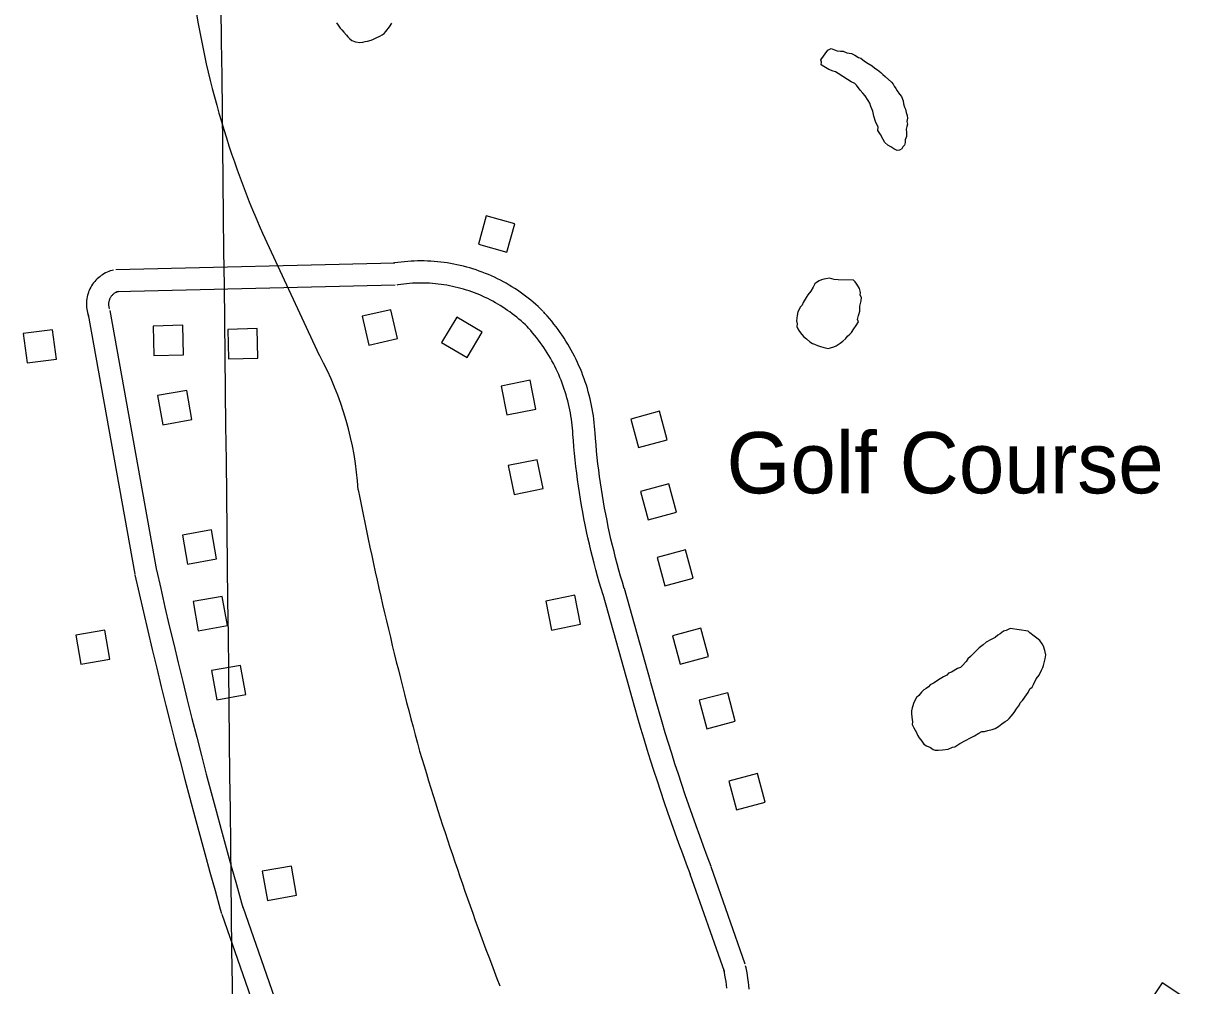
# Model space of a CAD drawing. Extents: x 3683402 to 3721514, y 487807 to 513565.
# Drawn here: x 3692628 to 3694204, y 495317 to 496621 of the extents above; entities that cross this region are included whole.
import ezdxf

# ---------------------------------------------------------------- set-up
doc = ezdxf.new("R2010")
doc.units = 0
for name, color, linetype in [('V-BLDG-IDEN', 7, 'Continuous'), ('V-BLDG-OTLN', 7, 'Continuous'), ('V-GRID-MAJR', 7, 'Continuous'), ('V-ROAD-CNTR', 7, 'Continuous'), ('V-TOPO-SHOR', 7, 'Continuous')]:
    doc.layers.add(name, color=color, linetype=linetype)

msp = doc.modelspace()

# ---------------------------------------------------------------- linework, layer by layer
at = {"layer": 'V-BLDG-OTLN'}
for points in [[(3693245, 496321.7), (3693283.6, 496311.1), (3693294.2, 496349.6), (3693255.6, 496360.3)], [(3693126.4, 496233), (3693087.4, 496224.2), (3693096.3, 496185.2), (3693135.2, 496194)], [(3693250, 496202.6), (3693215.7, 496223.1), (3693195.1, 496188.8), (3693229.5, 496168.2)], [(3692673.2, 496166.2), (3692668, 496205.9), (3692628.4, 496200.7), (3692633.5, 496161.1)], [(3692844.4, 496211.9), (3692804.4, 496210.9), (3692805.3, 496170.9), (3692845.3, 496171.9)], [(3692945.3, 496207.4), (3692905.3, 496206.4), (3692906.2, 496166.4), (3692946.2, 496167.4)], [(3693322.8, 496098.3), (3693315, 496137.5), (3693275.7, 496129.7), (3693283.5, 496090.5)], [(3692810.4, 496116.7), (3692817.5, 496077.3), (3692856.8, 496084.4), (3692849.8, 496123.8)], [(3693451.6, 496085), (3693461.9, 496046.4), (3693500.6, 496056.7), (3693490.2, 496095.4)], [(3693332.4, 495990.7), (3693324.6, 496029.9), (3693285.4, 496022.1), (3693293.2, 495982.9)], [(3693464.3, 495987), (3693474.7, 495948.4), (3693513.3, 495958.7), (3693502.9, 495997.4)], [(3692843.9, 495927.8), (3692850.9, 495888.5), (3692890.3, 495895.6), (3692883.2, 495934.9)], [(3693487, 495897.5), (3693497.3, 495858.9), (3693536, 495869.2), (3693525.6, 495907.9)], [(3692858.4, 495837.6), (3692865.5, 495798.2), (3692904.9, 495805.3), (3692897.8, 495844.7)], [(3693383.2, 495806.9), (3693375.4, 495846.2), (3693336.2, 495838.3), (3693344, 495799.1)], [(3692745.7, 495759.7), (3692738.8, 495799.1), (3692699.4, 495792.2), (3692706.3, 495752.8)], [(3693507.6, 495791.5), (3693518, 495752.8), (3693556.6, 495763.2), (3693546.2, 495801.8)], [(3692883.3, 495744.2), (3692890.4, 495704.8), (3692929.7, 495711.9), (3692922.7, 495751.2)], [(3693543.9, 495703.9), (3693554.3, 495665.2), (3693592.9, 495675.6), (3693582.6, 495714.2)], [(3693584.3, 495594.2), (3693594.7, 495555.6), (3693633.3, 495566), (3693623, 495604.6)], [(3692952.1, 495472.3), (3692959.2, 495432.9), (3692998.5, 495440), (3692991.5, 495479.4)], [(3694182.4, 495265.6), (3694204.4, 495299), (3694171, 495321), (3694149, 495287.6)]]:
    msp.add_lwpolyline(points, close=True, dxfattribs=at)
at = {"layer": 'V-GRID-MAJR'}
msp.add_spline([(3692934.8, 493283.3), (3692866.1, 499341.9), (3692797.3, 505402.5), (3692796.2, 505494.7)], degree=3, dxfattribs=at)
at = {"layer": 'V-ROAD-CNTR'}
for points in [[(3692952.5, 496336.6), (3693029.4, 496171.4)], [(3693131.6, 496296.3), (3692753.8, 496287.3)], [(3693332.3, 496231.1), (3693329.2, 496234.2), (3693326, 496237.2), (3693322.6, 496240.2), (3693319.3, 496243.2), (3693315.8, 496246), (3693312.3, 496248.8), (3693308.8, 496251.6), (3693305.2, 496254.2), (3693301.6, 496256.8), (3693297.9, 496259.4), (3693294.1, 496261.8), (3693290.3, 496264.2), (3693286.5, 496266.5), (3693282.6, 496268.8), (3693278.7, 496270.9), (3693274.8, 496273), (3693270.8, 496275), (3693266.7, 496277), (3693262.7, 496278.8), (3693258.5, 496280.6), (3693254.4, 496282.3), (3693250.2, 496283.9), (3693246, 496285.5), (3693241.8, 496286.9), (3693237.5, 496288.3), (3693233.3, 496289.6), (3693229, 496290.9), (3693224.6, 496292), (3693220.3, 496293), (3693215.9, 496294), (3693211.5, 496294.9), (3693207.1, 496295.7), (3693202.7, 496296.4), (3693198.3, 496297.1), (3693193.8, 496297.6), (3693189.4, 496298.1), (3693184.9, 496298.5), (3693180.5, 496298.7), (3693176, 496299), (3693171.5, 496299.1), (3693167, 496299.1), (3693162.6, 496299.1), (3693158.1, 496298.9), (3693153.6, 496298.7), (3693149.2, 496298.4), (3693144.7, 496298), (3693140.2, 496297.6), (3693135.8, 496297), (3693131.4, 496296.4), (3693129.6, 496296.1)], [(3692750.5, 496286.8), (3692748.6, 496286.3), (3692746.3, 496285.6), (3692744.1, 496284.8), (3692741.9, 496283.9), (3692739.8, 496282.9), (3692737.7, 496281.8), (3692735.7, 496280.5), (3692733.8, 496279.2), (3692731.9, 496277.8), (3692730.1, 496276.3), (3692728.3, 496274.7), (3692726.7, 496273), (3692725.1, 496271.2), (3692723.6, 496269.4), (3692722.3, 496267.5), (3692721, 496265.5), (3692719.8, 496263.5), (3692718.7, 496261.4), (3692717.7, 496259.2), (3692716.8, 496257.1), (3692716.1, 496254.8), (3692715.4, 496252.6), (3692714.9, 496250.3), (3692714.5, 496247.9), (3692714.1, 496245.6), (3692714, 496243.3), (3692713.9, 496240.9), (3692713.9, 496238.5), (3692714.1, 496236.2), (3692714.3, 496233.8), (3692714.7, 496231.5), (3692715.2, 496229.2), (3692715.8, 496226.9), (3692716.5, 496224.8), (3692716.7, 496224.3)], [(3693132.3, 496266.3), (3692754.6, 496257.3)], [(3693311.4, 496209.7), (3693308.5, 496212.5), (3693305.6, 496215.1), (3693302.7, 496217.8), (3693299.8, 496220.3), (3693296.8, 496222.8), (3693293.8, 496225.3), (3693290.7, 496227.7), (3693287.5, 496230), (3693284.4, 496232.2), (3693281.1, 496234.4), (3693277.9, 496236.6), (3693274.6, 496238.7), (3693271.2, 496240.7), (3693267.9, 496242.6), (3693264.4, 496244.5), (3693261, 496246.4), (3693257.5, 496248.1), (3693254, 496249.8), (3693250.4, 496251.4), (3693246.9, 496253), (3693243.3, 496254.5), (3693239.6, 496255.9), (3693236, 496257.2), (3693232.3, 496258.5), (3693228.6, 496259.7), (3693224.8, 496260.8), (3693221.1, 496261.9), (3693217.3, 496262.9), (3693213.5, 496263.8), (3693209.7, 496264.7), (3693205.9, 496265.4), (3693202, 496266.1), (3693198.2, 496266.8), (3693194.3, 496267.3), (3693190.4, 496267.8), (3693186.6, 496268.2), (3693182.7, 496268.5), (3693178.8, 496268.8), (3693174.9, 496269), (3693171, 496269.1), (3693167.1, 496269.1), (3693163.2, 496269.1), (3693159.3, 496269), (3693155.4, 496268.8), (3693151.5, 496268.5), (3693147.6, 496268.2), (3693143.7, 496267.8), (3693139.8, 496267.3), (3693135.9, 496266.7), (3693134.3, 496266.4)], [(3692757.9, 496257.7), (3692756.7, 496257.4), (3692755.9, 496257.2), (3692755.1, 496256.9), (3692754.3, 496256.5), (3692753.5, 496256.2), (3692752.7, 496255.8), (3692752, 496255.3), (3692751.2, 496254.8), (3692750.5, 496254.3), (3692749.9, 496253.7), (3692749.2, 496253.1), (3692748.6, 496252.5), (3692748, 496251.9), (3692747.5, 496251.2), (3692747, 496250.5), (3692746.5, 496249.7), (3692746.1, 496249), (3692745.7, 496248.2), (3692745.3, 496247.4), (3692745, 496246.6), (3692744.7, 496245.8), (3692744.5, 496245), (3692744.3, 496244.1), (3692744.1, 496243.3), (3692744, 496242.4), (3692743.9, 496241.5), (3692743.9, 496240.6), (3692743.9, 496239.8), (3692744, 496238.9), (3692744.1, 496238), (3692744.2, 496237.2), (3692744.4, 496236.3), (3692744.6, 496235.5), (3692744.9, 496234.5), (3692745, 496234.4)], [(3692745.6, 496232), (3692808.9, 495879.9)], [(3692716.1, 496226.7), (3692779.3, 495874.6)], [(3693402.9, 496066), (3693402.6, 496070.5), (3693402.2, 496075.2), (3693401.7, 496079.9), (3693401.2, 496084.6), (3693400.6, 496089.3), (3693399.8, 496094), (3693399, 496098.6), (3693398.1, 496103.3), (3693397.2, 496107.9), (3693396.1, 496112.5), (3693395, 496117.1), (3693393.8, 496121.6), (3693392.5, 496126.2), (3693391.1, 496130.7), (3693389.6, 496135.2), (3693388.1, 496139.6), (3693386.5, 496144.1), (3693384.8, 496148.5), (3693383, 496152.8), (3693381.1, 496157.2), (3693379.2, 496161.5), (3693377.2, 496165.7), (3693375.1, 496170), (3693372.9, 496174.2), (3693370.7, 496178.3), (3693368.4, 496182.4), (3693366, 496186.5), (3693363.5, 496190.5), (3693361, 496194.5), (3693358.4, 496198.5), (3693355.7, 496202.4), (3693353, 496206.2), (3693350.2, 496210), (3693347.3, 496213.7), (3693344.3, 496217.4), (3693341.3, 496221), (3693338.2, 496224.6), (3693335.1, 496228.1), (3693332.9, 496230.5)], [(3693372.9, 496064.1), (3693372.7, 496068.4), (3693372.3, 496072.5), (3693371.9, 496076.7), (3693371.4, 496080.9), (3693370.9, 496085), (3693370.2, 496089.1), (3693369.5, 496093.3), (3693368.7, 496097.4), (3693367.9, 496101.5), (3693366.9, 496105.5), (3693365.9, 496109.6), (3693364.9, 496113.6), (3693363.7, 496117.6), (3693362.5, 496121.6), (3693361.2, 496125.6), (3693359.8, 496129.6), (3693358.4, 496133.5), (3693356.9, 496137.4), (3693355.3, 496141.3), (3693353.7, 496145.1), (3693351.9, 496148.9), (3693350.2, 496152.7), (3693348.3, 496156.5), (3693346.4, 496160.2), (3693344.4, 496163.9), (3693342.4, 496167.5), (3693340.2, 496171.1), (3693338.1, 496174.7), (3693335.8, 496178.2), (3693333.5, 496181.7), (3693331.1, 496185.1), (3693328.7, 496188.5), (3693326.2, 496191.9), (3693323.7, 496195.2), (3693321.1, 496198.5), (3693318.4, 496201.7), (3693315.7, 496204.9), (3693312.9, 496208), (3693310.8, 496210.2)], [(3693413.8, 495846.8), (3693411.2, 495855.2), (3693408.7, 495863.8), (3693406.3, 495872.3), (3693403.9, 495880.9), (3693401.7, 495889.5), (3693399.5, 495898.1), (3693397.3, 495906.8), (3693395.3, 495915.5), (3693393.3, 495924.1), (3693391.5, 495932.8), (3693389.7, 495941.6), (3693387.9, 495950.3), (3693386.3, 495959), (3693384.7, 495967.8), (3693383.3, 495976.6), (3693381.9, 495985.4), (3693380.5, 495994.2), (3693379.3, 496003), (3693378.1, 496011.8), (3693377.1, 496020.6), (3693376.1, 496029.5), (3693375.1, 496038.3), (3693374.3, 496047.2), (3693373.6, 496056.1), (3693373, 496063.9)], [(3693442.5, 495855.5), (3693440, 495863.8), (3693437.5, 495872.1), (3693435.2, 495880.4), (3693432.9, 495888.7), (3693430.7, 495897.1), (3693428.6, 495905.4), (3693426.5, 495913.8), (3693424.5, 495922.2), (3693422.6, 495930.6), (3693420.8, 495939), (3693419.1, 495947.5), (3693417.4, 495956), (3693415.8, 495964.4), (3693414.3, 495972.9), (3693412.9, 495981.4), (3693411.5, 495989.9), (3693410.2, 495998.5), (3693409, 496007), (3693407.9, 496015.6), (3693406.9, 496024.1), (3693405.9, 496032.7), (3693405, 496041.3), (3693404.2, 496049.9), (3693403.5, 496058.5), (3693402.9, 496066.2)], [(3692779.5, 495873.9), (3692785.2, 495848.6), (3692791.1, 495823.3), (3692797, 495798.1), (3692803, 495772.8), (3692809.1, 495747.6), (3692815.3, 495722.3), (3692821.5, 495697.1), (3692827.8, 495671.9), (3692834.2, 495646.8), (3692840.7, 495621.6), (3692847.2, 495596.5), (3692853.9, 495571.4), (3692860.6, 495546.3), (3692867.4, 495521.3), (3692874.2, 495496.2), (3692881.2, 495471.2), (3692888.2, 495446.2), (3692895.3, 495421.2), (3692897, 495415)], [(3692808.7, 495880.6), (3692814.5, 495855.3), (3692820.3, 495830.1), (3692826.2, 495805), (3692832.2, 495779.8), (3692838.3, 495754.6), (3692844.4, 495729.5), (3692850.6, 495704.4), (3692856.9, 495679.3), (3692863.3, 495654.2), (3692869.7, 495629.2), (3692876.3, 495604.1), (3692882.9, 495579.1), (3692889.5, 495554.1), (3692896.3, 495529.1), (3692903.1, 495504.2), (3692910.1, 495479.3), (3692917, 495454.4), (3692924.1, 495429.5), (3692925.9, 495423.2)], [(3693477.9, 495729.7), (3693442.6, 495855.2)], [(3693449, 495721.6), (3693413.7, 495847.1)], [(3693560.1, 495478.8), (3693554.9, 495492.6), (3693549.7, 495506.4), (3693544.7, 495520.2), (3693539.7, 495534.1), (3693534.7, 495548), (3693529.9, 495561.9), (3693525.1, 495575.9), (3693520.4, 495589.8), (3693515.8, 495603.8), (3693511.2, 495617.8), (3693506.8, 495631.9), (3693502.4, 495646), (3693498, 495660), (3693493.8, 495674.2), (3693489.6, 495688.3), (3693485.5, 495702.5), (3693481.5, 495716.6), (3693477.9, 495729.6)], [(3693532.1, 495468.1), (3693526.8, 495482), (3693521.6, 495496), (3693516.5, 495510), (3693511.4, 495524), (3693506.4, 495538), (3693501.5, 495552.1), (3693496.7, 495566.2), (3693491.9, 495580.3), (3693487.3, 495594.5), (3693482.7, 495608.7), (3693478.1, 495622.9), (3693473.7, 495637.1), (3693469.3, 495651.3), (3693465, 495665.6), (3693460.8, 495679.9), (3693456.7, 495694.2), (3693452.6, 495708.5), (3693449, 495721.6)], [(3693606.4, 495346.4), (3693560.3, 495478.4)], [(3693578.1, 495336.5), (3693531.9, 495468.5)], [(3692897.3, 495414.2), (3692968.6, 495209.4)], [(3692925.6, 495424), (3692997, 495219.2)], [(3693581.4, 495314.2), (3693580.9, 495318.6), (3693580.3, 495322.9), (3693579.6, 495327.2), (3693578.9, 495331.5), (3693578.1, 495335.8), (3693577.5, 495338.4)], [(3693611.7, 495312.6), (3693611.2, 495317.5), (3693610.6, 495322.3), (3693610, 495327.2), (3693609.2, 495332), (3693608.4, 495336.8), (3693607.5, 495341.5), (3693606.9, 495344.4)]]:
    msp.add_lwpolyline(points, dxfattribs=at)
for centre, radius, start, end in [((3694086.7, 496840.2), 1241, 186.8966, 203.9404), ((3692643.8, 495961.5), 439.1, 3.6165, 28.5606), ((3697884.3, 496932.6), 4894.1, 191.1142, 195.3734), ((3697160.6, 496821.2), 4167.6, 196.5342, 201.1525)]:
    msp.add_arc(centre, radius, start, end, dxfattribs=at)
at = {"layer": 'V-TOPO-SHOR'}
for points in [[(3693052.5, 496621.9), (3693054.9, 496618.7), (3693057.8, 496614.5), (3693060, 496612.3), (3693062.4, 496609.1), (3693066.1, 496605.2), (3693068, 496602.8), (3693070.9, 496599.8), (3693073.6, 496597.8), (3693078.5, 496596.1), (3693084.1, 496595.1), (3693088.5, 496595.6), (3693091.7, 496596.3), (3693094.8, 496596.7), (3693099.7, 496598.4), (3693102.7, 496599.6), (3693106.3, 496601.3), (3693111.2, 496603.7), (3693114.7, 496605.4), (3693117.1, 496607.4), (3693119.3, 496609.8), (3693124.3, 496616.1), (3693127.5, 496621.2)], [(3693718.2, 496584.8), (3693722.7, 496586.9), (3693727.2, 496585.3), (3693730.9, 496583.7), (3693735.3, 496583.5), (3693739.1, 496583.4), (3693744.2, 496581), (3693750.2, 496580.1), (3693754.6, 496577.7), (3693759.8, 496574.6), (3693762.8, 496573.7), (3693767.9, 496569.8), (3693773, 496566.7), (3693778.2, 496563.5), (3693781.8, 496560.4), (3693785.5, 496558.1), (3693789.9, 496554.2), (3693792.8, 496551.9), (3693795.7, 496548.8), (3693804.4, 496541.1), (3693806.6, 496538.8), (3693808, 496535.7), (3693810.2, 496532.7), (3693812.3, 496529.6), (3693815.2, 496525), (3693818.1, 496521.9), (3693820.2, 496515.9), (3693820.8, 496512.1), (3693822.2, 496507.6), (3693823.6, 496504.6), (3693824.2, 496500.1), (3693825.6, 496496.3), (3693826.2, 496492.5), (3693825.3, 496488), (3693826, 496484.3), (3693825.1, 496481.3), (3693824.3, 496477.6), (3693824.9, 496473.1), (3693824.7, 496467.9), (3693823.1, 496463.4), (3693823, 496459.7), (3693822.1, 496456), (3693819.8, 496453.8), (3693818.3, 496450.8), (3693815.2, 496449.4), (3693812.2, 496448.8), (3693807.8, 496451.1), (3693803.4, 496453.5), (3693799.7, 496455.9), (3693795.3, 496459.7), (3693793.2, 496463.5), (3693789.6, 496470.4), (3693786.1, 496475.7), (3693786.2, 496481), (3693784.1, 496484.8), (3693782.7, 496487.8), (3693780.6, 496495.4), (3693779.3, 496502.1), (3693777.9, 496505.2), (3693776.5, 496508.2), (3693775.2, 496512.7), (3693773, 496516.5), (3693768.7, 496522.7), (3693765.8, 496526.5), (3693762.2, 496530.3), (3693757.2, 496537.2), (3693755, 496539.5), (3693749.8, 496541.9), (3693744.7, 496545.1), (3693732.2, 496552.9), (3693728.5, 496555.3), (3693725.6, 496556.1), (3693719.6, 496558.5), (3693713, 496562.5), (3693709.3, 496564.8), (3693709.5, 496568.6), (3693708.8, 496571.6), (3693718.2, 496584.8)], [(3693732.2, 496273.7), (3693726.9, 496273.9), (3693720.3, 496275.6), (3693715.7, 496275), (3693712.7, 496274.3), (3693709.7, 496273.6), (3693706.7, 496272.2), (3693702.9, 496270.1), (3693700.6, 496267.9), (3693698.2, 496263.5), (3693695, 496258.4), (3693691.2, 496253.2), (3693688.8, 496249.6), (3693684.9, 496242.9), (3693683.3, 496239.2), (3693680.9, 496236.3), (3693679.3, 496233.4), (3693677.8, 496230.4), (3693676.9, 496225.2), (3693675.9, 496217.8), (3693676.5, 496214), (3693676.4, 496210.3), (3693677.8, 496207.2), (3693679.9, 496203.4), (3693682.8, 496199.6), (3693685.7, 496196.5), (3693689.4, 496193.4), (3693693.8, 496189.5), (3693697.4, 496187.2), (3693700.4, 496186.3), (3693704.1, 496184.7), (3693708.5, 496183.1), (3693711.5, 496182.3), (3693715.2, 496181.4), (3693718.9, 496180.6), (3693722, 496181.2), (3693726.5, 496182.6), (3693729.5, 496184), (3693734.9, 496187.6), (3693738.7, 496190.4), (3693742.5, 496194.1), (3693744.9, 496197), (3693748, 496199.9), (3693750.3, 496202.1), (3693753.4, 496207.2), (3693756.5, 496211.6), (3693759.7, 496216.8), (3693758.3, 496219.8), (3693759.9, 496225), (3693760.8, 496228), (3693761.6, 496230.9), (3693761.8, 496237.7), (3693762.7, 496241.4), (3693763.5, 496245.1), (3693763.7, 496249.6), (3693762.2, 496252.6), (3693762.4, 496256.4), (3693761, 496261.6), (3693757.5, 496267.7), (3693755.3, 496270.8), (3693753.1, 496273.1), (3693732.2, 496273.7)], [(3693965.2, 495801.3), (3693959.9, 495798.4), (3693956.1, 495797.8), (3693951.5, 495794.2), (3693948.5, 495792), (3693944.7, 495789.1), (3693939.3, 495786.3), (3693932.5, 495782.8), (3693928.6, 495779.1), (3693923.3, 495774.8), (3693921, 495772.6), (3693918.7, 495770.4), (3693915.6, 495767.5), (3693911.7, 495763.2), (3693907.9, 495760.3), (3693905.5, 495756.6), (3693900.1, 495750.8), (3693897.8, 495748.6), (3693894, 495747.2), (3693885.6, 495742.2), (3693881.9, 495740.8), (3693879.5, 495737.9), (3693875, 495735.8), (3693870.4, 495733), (3693861.2, 495727.2), (3693856.7, 495725.1), (3693854.4, 495722.2), (3693851.3, 495720), (3693848.2, 495717.9), (3693845.2, 495715), (3693841.3, 495710.6), (3693838.2, 495707.7), (3693836.6, 495704.8), (3693834.2, 495699.6), (3693833.4, 495696.6), (3693832.6, 495693.6), (3693831.7, 495689.9), (3693831.6, 495686.2), (3693832.2, 495680.9), (3693832.8, 495674.9), (3693832.6, 495671.2), (3693834.8, 495666.6), (3693838.3, 495660.5), (3693839.7, 495656.8), (3693841.8, 495653), (3693845.4, 495648.4), (3693848.3, 495644.5), (3693852, 495642.2), (3693857.2, 495639.8), (3693860.8, 495637.4), (3693863.8, 495636.6), (3693867.5, 495636.5), (3693873.6, 495637), (3693881.1, 495637.6), (3693887.1, 495640.4), (3693890.1, 495641), (3693897, 495645.3), (3693904.6, 495649.6), (3693911.5, 495653.1), (3693916.8, 495656), (3693922.9, 495659.5), (3693926.7, 495661.7), (3693930.4, 495661.6), (3693934.9, 495662.9), (3693941, 495664.2), (3693944.8, 495665.6), (3693949.3, 495668.5), (3693953.9, 495672.1), (3693958.5, 495675), (3693961.6, 495677.1), (3693963.9, 495679.3), (3693967, 495682.9), (3693970.8, 495687.3), (3693974, 495692.5), (3693977.9, 495697.6), (3693978.7, 495700.6), (3693981.8, 495703.5), (3693987.3, 495711.5), (3693989.6, 495714.5), (3693992, 495719.6), (3693995.1, 495721.8), (3693996.7, 495725.5), (3694000.6, 495732.8), (3694004.5, 495738), (3694007.7, 495744.6), (3694009.3, 495748.3), (3694010.2, 495751.3), (3694011.8, 495756.5), (3694012.7, 495760.2), (3694013.6, 495765.4), (3694012.3, 495771.4), (3694010.2, 495777.5), (3694008.8, 495780.5), (3694005.2, 495785.1), (3694001.5, 495788.2), (3693997.9, 495790.6), (3693992, 495795.2), (3693989.8, 495797.5), (3693965.2, 495801.3)]]:
    msp.add_lwpolyline(points, dxfattribs=at)

# ---------------------------------------------------------------- texts
at = {"layer": 'V-BLDG-IDEN'}
msp.add_text('Golf Course', height=83, dxfattribs=at).set_placement((3693581.1, 495984.3))

doc.saveas('drawing.dxf')
